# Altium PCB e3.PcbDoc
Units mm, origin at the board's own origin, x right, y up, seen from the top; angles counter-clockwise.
Board outline 100 x 60 mm, 2 copper layers (Top Layer, Bottom Layer), stack 0.325 mm thick; 68 components, 138 nets, 434 pads, 129 vias.
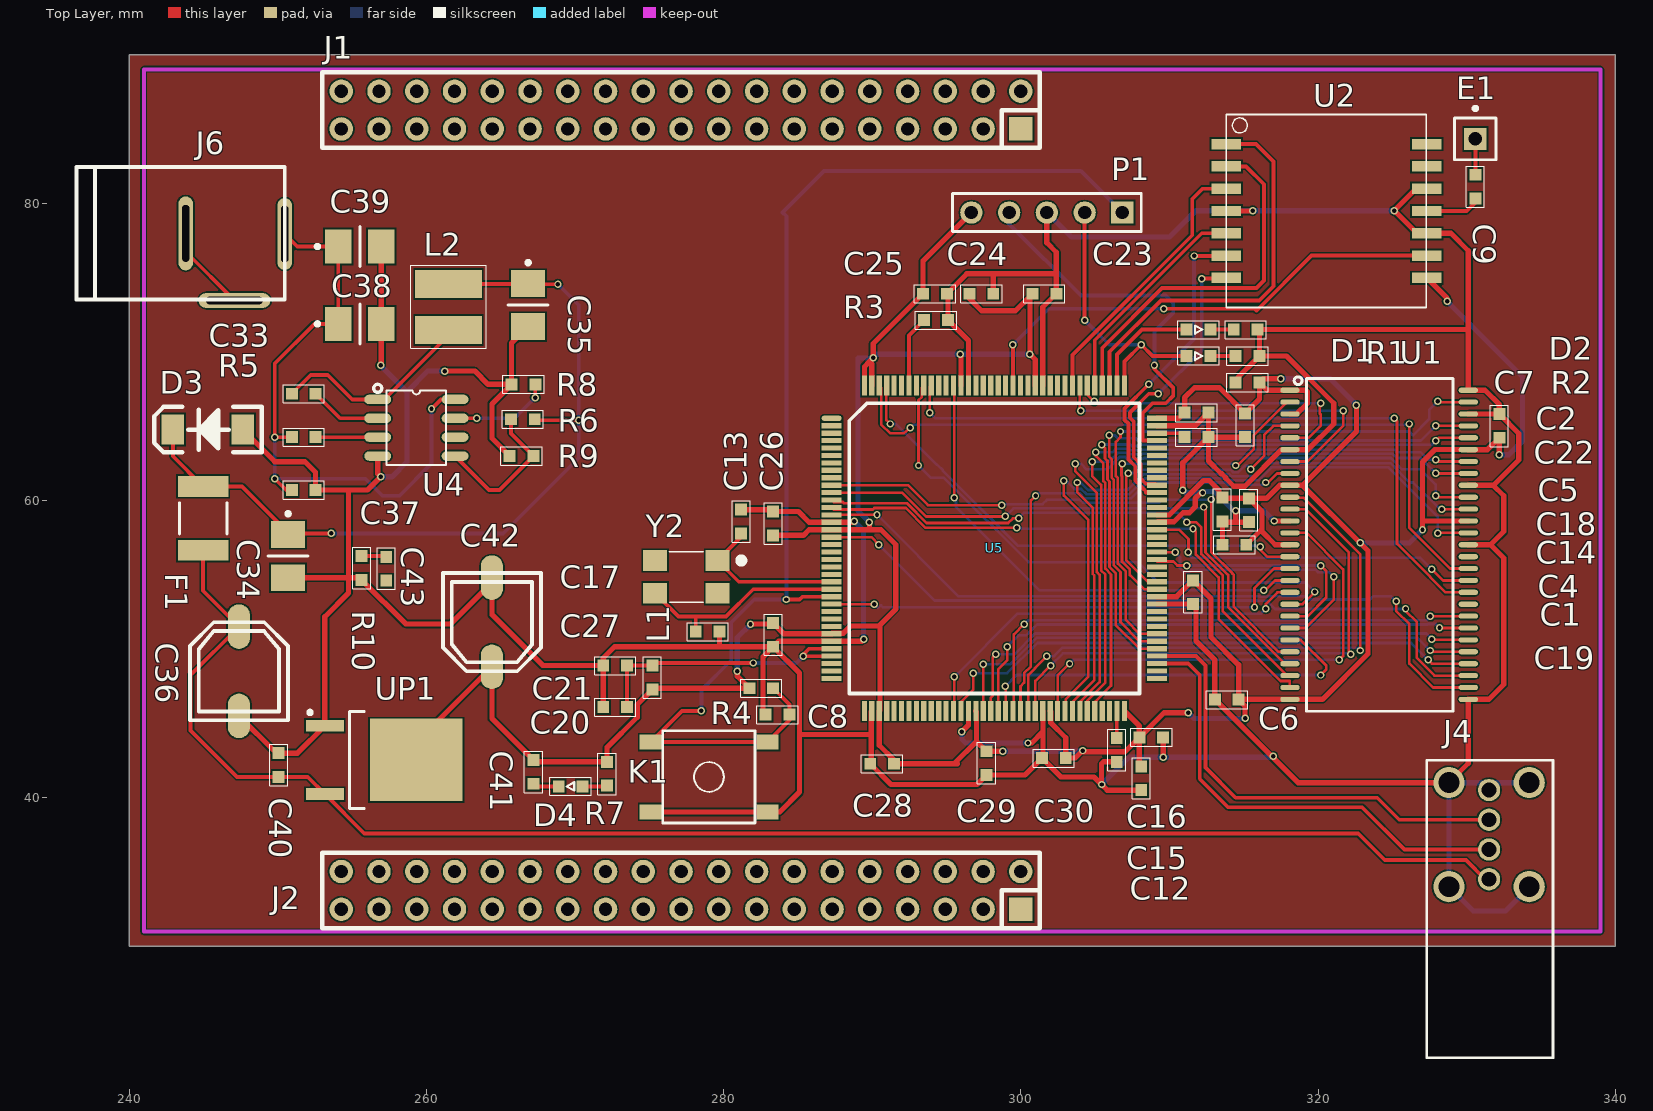
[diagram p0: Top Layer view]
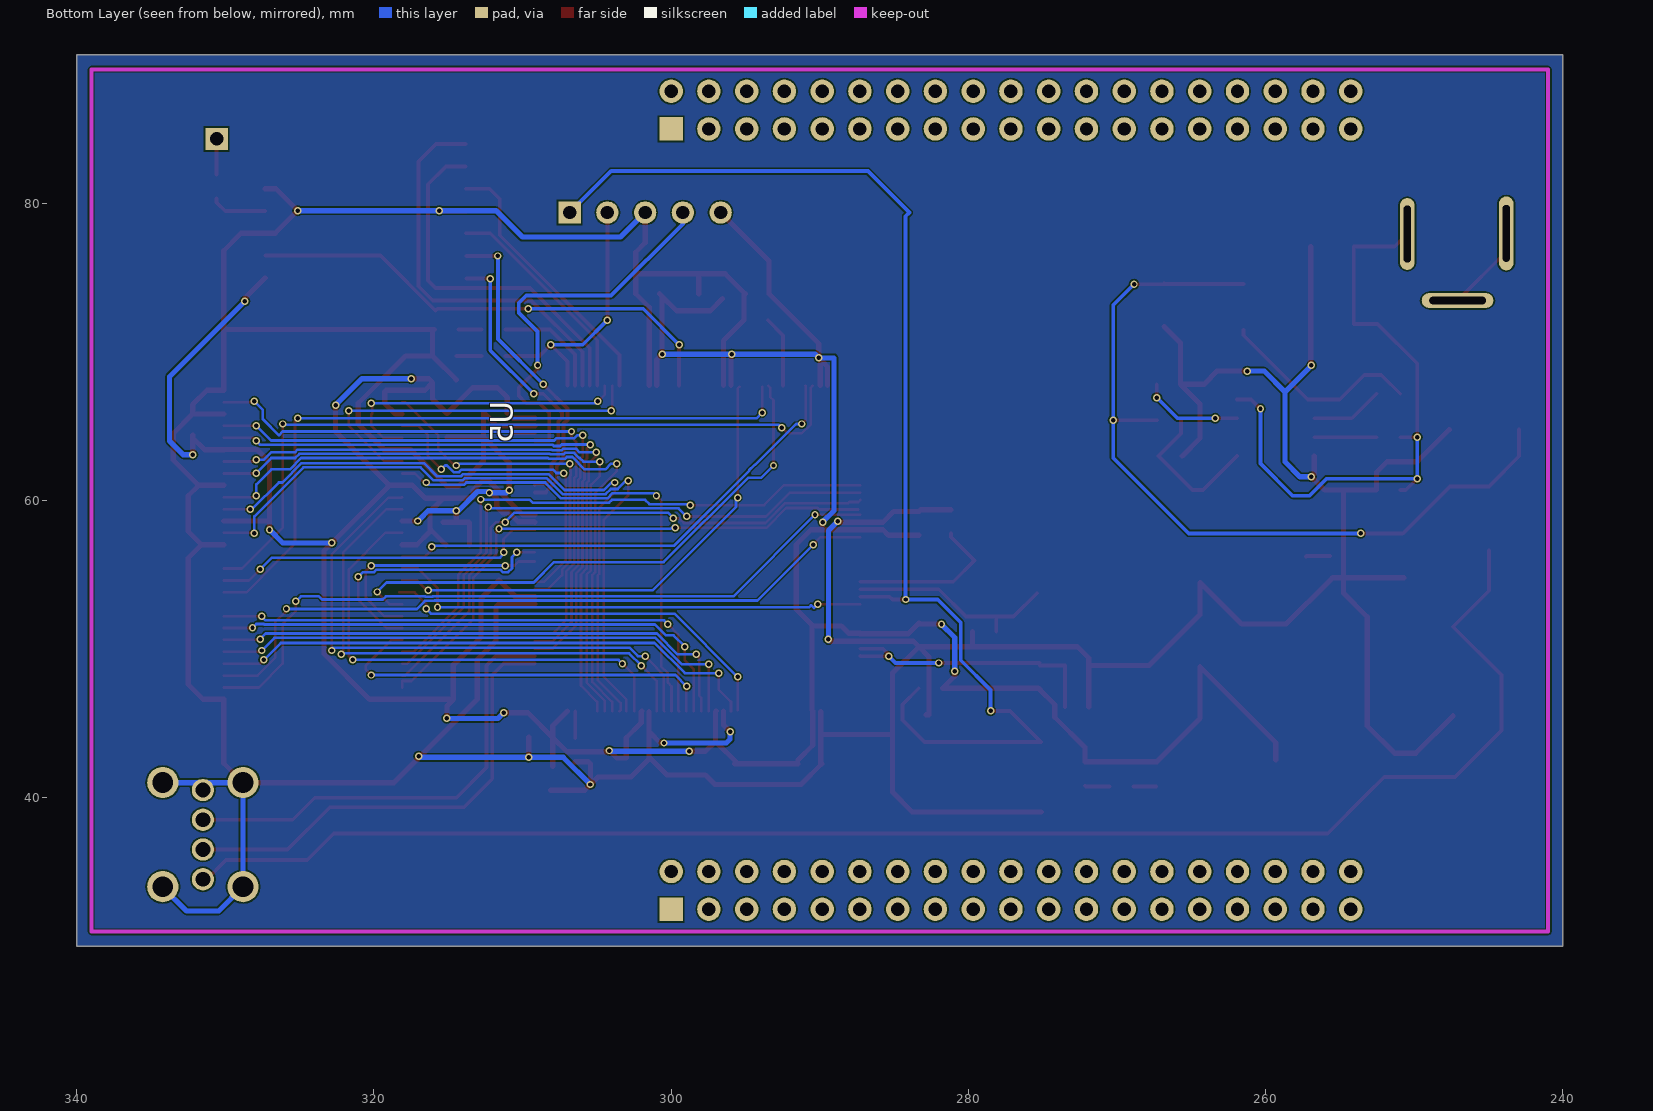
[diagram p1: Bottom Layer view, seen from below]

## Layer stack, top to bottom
Top Solder: solder mask 0.0102, Solder Resist, Dk 3.5
Top Layer: signal copper 0.0356
Dielectric 1: core 0.254, FR-4, Dk 4.2
Bottom Layer: signal copper 0.0356
Bottom Solder: solder mask 0.0102, Solder Resist, Dk 3.5

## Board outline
240,30 240,90 340,90 340,30

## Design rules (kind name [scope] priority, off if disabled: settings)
Clearance GND [All] p1: gap=0.104
HoleSize [All] p1: absolutevalues=TRUE maxlimit=4.5 minlimit=0.3 maxpercent=80.000 minpercent=20.000
HoleToHoleClearance [All] p1: gap=0.1 allowstackedmicrovias=TRUE
MinimumSolderMaskSliver [All] p1: minsoldermaskwidth=0.01
PolygonConnect [IsVia] p1: connectstyle=Direct reliefconductorwidth=0.254 reliefentries=4 polygonreliefangle="90 Angle" airgapwidth=0.254
RoomDefinition Sheet1 [InComponentClass('Sheet1')] p1: confinementstyle=ConfineIn formatcopy=TRUE lockcomponents=FALSE outline 235.077,0 337.185,0 337.185,91.44 235.077,91.44
RoutingVias [All] p1: holewidth=0.3 width=0.5 viastyle="Through Hole" minholewidth=0.1 minwidth=0.3 maxholewidth=0.6 maxwidth=1
SilkToSilkClearance [All] p1: silktosilkclearance=0.01
SilkToSolderMaskClearance [IsPad] p1: minsilkscreentomaskgap=0 clearancetoexposedcopper=FALSE
SolderMaskExpansion [All] p1: expansion=0.102
Width Width_3 [InNetClass('SDIO')] p1: maxlimit=0.254 minlimit=0.254 preferedwidth=0.254
Width Width_1 [InNetClass('SDRAM')] p2: maxlimit=0.254 minlimit=0.153 preferedwidth=0.177
Width Width_2 [InNet('GND')] p3: maxlimit=0.454 minlimit=0.254 preferedwidth=0.354
Width [InNet('3.3V')] p4: maxlimit=0.354 minlimit=0.254 preferedwidth=0.354
25 further rules are at their usual default settings.

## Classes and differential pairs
component class Sheet1: C2 C5 C6 C7 C8 C9 C12 C13 C15 C16 C17 C20 C21 C22 C23 C24 C25 C26 C27 C28 C29 C30 C33 C34 C35 C36 C37 C38 C39 C40 C41 C42 C43 D1 D2 D3 D4 E1 F1 J1 J2 J4 J6 K1 L1 L2 P1 R1 R2 R3 R4 R5 R6 R7 R8 R9 R10 U1 U2 U4 U5 UP1 Y2
net class WIFI: NetU2_1 NetU2_2 NetU2_3 NetU2_5 NetU2_6 NetU2_7 NetU2_9
net class SDRAM: NetU1_2 NetU1_4 NetU1_5 NetU1_7 NetU1_8 NetU1_10 NetU1_11 NetU1_13 NetU1_15 NetU1_16 NetU1_17 NetU1_18 NetU1_19 NetU1_20 NetU1_21 NetU1_22 NetU1_23 NetU1_24 NetU1_25 NetU1_26 NetU1_29 NetU1_30 NetU1_31 NetU1_32 NetU1_33 NetU1_34 NetU1_35 NetU1_37 NetU1_38 NetU1_39 NetU1_42 NetU1_44 NetU1_45 NetU1_47 NetU1_48 NetU1_50 NetU1_51 NetU1_53

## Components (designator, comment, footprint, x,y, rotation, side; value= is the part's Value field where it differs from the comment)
C1 "C_0.1UF_0603" C_0603 313.563,57.023 r0 top
C2 "C_0.1UF_0603" C_0603 314.452,67.945 r0 top
C4 "C_0.1UF_0603" C_0603 315.341,58.547 r90 top
C5 "C_0.1UF_0603" C_0603 315.087,64.262 r90 top
C6 "C_0.1UF_0603" C_0603 313.055,46.609 r0 top
C7 "C_0.1UF_0603" C_0603 332.195,65.823 r270 top
C8 "C_0.1UF_0603" C_0603 282.829,45.593 r0 top
C9 "CAP_NP" R_0603 330.581,81.915 r270 top
C12 "C_2.2UF_0603" CAP_0603_FIRE 306.451,42.418 r90 top
C13 "C_22P_0603" C_0603 281.178,57.785 r90 top
C14 "C_2.2UF_0603" CAP_0603_FIRE 311.023,64.262 r0 top
C15 "C_0.1UF_0603" C_0603 307.975,44.069 r0 top
C16 "C_0.1UF_0603" C_0603 308.102,40.513 r90 top
C17 "C_22P_0603" C_0603 278.13,51.181 r0 top
C18 "C_0.1UF_0603" C_0603 313.563,60.198 r270 top
C19 "C_0.1UF_0603" C_0603 311.585,53.032 r90 top
C20 "C_0.1UF_0603" C_0603 271.907,46.101 r0 top
C21 "C_0.1UF_0603" C_0603 271.907,48.895 r0 top
C22 "C_0.1UF_0603" C_0603 311.023,65.913 r0 top
C23 "C_0.1UF_0603" C_0603 302.387,73.914 r180 top
C24 "C_0.1UF_0603" C_0603 296.545,73.914 r0 top
C25 "C_0.1UF_0603" C_0603 295.021,73.914 r180 top
C26 "C_0.1UF_0603" C_0603 283.337,57.658 r90 top
C27 "C_0.1UF_0603" C_0603 283.337,50.165 r90 top
C28 "C_0.1UF_0603" C_0603 291.465,42.291 r180 top
C29 "C_0.1UF_0603" C_0603 297.688,41.529 r90 top
C30 "C_0.1UF_0603" C_0603 303.022,42.672 r180 top
C33 "C_0.1UF_0603" C_0603 250.952,67.183 r0 top
C34 "C+_10UF_B" AVX_B_3528-21 250.698,56.261 r270 top
C35 "C+_10UF_B" AVX_B_3528-21 266.849,73.152 r270 top
C36 "CAP+_47UF_6.5X6.5" EC_47UF_6.5X6.5 247.396,48.514 r0 top
C37 "C_0.1UF_0603" C_0603 250.952,60.706 r0 top
C38 "C+_10UF_B" AVX_B_3528-21 255.524,71.882 r0 top
C39 "C+_10UF_B" AVX_B_3528-21 255.524,77.089 r0 top
C40 "C_0.1UF_0603" C_0603 250.063,41.402 r90 top
C41 "C_0.1UF_0603" C_0603 267.208,42.545 r270 top
C42 "CAP+_47UF_6.5X6.5" EC_47UF_6.5X6.5 264.414,51.816 r180 top
C43 "C_2.7NF_0603" C_0603 257.302,54.61 r90 top
D1 "LED_BLUE_0603" LED_0603 311.15,71.501 r0 top
D2 "LED_RED_0603" LED_0603 311.15,69.723 r0 top
D3 "SMAJ5.0CA" DO-214 247.65,64.77 r180 top
D4 "LED_RED_0603" LED_0603 270.51,40.767 r180 top
E1 "Antenna" PIN1 330.581,84.328 r0 top
F1 "FUSE500MA" C1812 244.983,58.801 r270 top
J1 "2X19PIN_DIP" 2X19X2.54MM 300,85 r90 top
J2 "2X19PIN_DIP" 2X19X2.54MM 300,32.5 r90 top
J4 "USB-AF90" USB-AF90 328.803,41.021 r270 top
J6 "DC-005" DC-005 236.474,73.533 r0 top
K1 "KEY" SW6.2/6.2-SMD 279.019,41.402 r0 top
L1 "BEAD-0603" R_0603 275.209,48.895 r270 top
L2 "L_6.8UH_4532" GDCD4532 261.493,73.025 r90 top
P1 "Header 5" HDR1X5 306.832,79.375 r180 top
R1 "R_1K_0603" R_0603 314.325,71.501 r0 top
R2 "R_1K_0603" R_0603 314.452,69.723 r0 top
R3 "R_10K_0603" R_0603 293.497,72.136 r0 top
R4 "R_10K_0603" R_0603 283.337,47.371 r180 top
R5 "R_100K_0603" R_0603 250.952,64.262 r0 top
R6 "R_62K_0603" R_0603 267.297,65.468 r180 top
R7 "R_1K_0603" R_0603 272.161,42.418 r270 top
R8 "R_180K_0603" R_0603 267.335,67.818 r180 top
R9 "R_11.8K_0603" R_0603 267.208,62.992 r180 top
R10 "R_24K_0603" R_0603 255.651,56.261 r270 top
U1 "IS42S16400J" TSOP-54 324.104,57.023 r0 top
U2 "BL-8782" BL-8782 313.817,85.979 r0 top
U4 "RT7272" RT7272 259.334,64.897 r0 top
U5 "STM32F429_144" 429_144 287.274,65.532 r0 top
UP1 "1086-3.3" TO-252-2L 257.175,42.545 r0 top
Y2 "CRYSTAL_25MHZ" CRYSTAL_25MHZ 277.495,54.864 r180 top

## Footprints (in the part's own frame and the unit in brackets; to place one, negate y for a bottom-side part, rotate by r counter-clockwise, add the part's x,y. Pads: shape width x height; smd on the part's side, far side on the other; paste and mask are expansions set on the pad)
2X19X2.54MM [mil]
  rrect0% 62x62 all layers, no hole: 1(0,0)
  round 62 hole 35.43: 2(100,0) 3(0,100) 4(100,100) 5(0,200) 6(100,200) 7(0,300) 8(100,300) 9(0,400) 10(100,400) 11(0,500) 12(100,500) 13(0,600) 14(100,600) 15(0,700) 16(100,700) 17(0,800) 18(100,800) 19(0,900) 20(100,900) 21(0,1000) 22(100,1000) 23(0,1100) 24(100,1100) 25(0,1200) 26(100,1200) 27(0,1300) 28(100,1300) 29(0,1400) 30(100,1400) 31(0,1500) 32(100,1500) 33(0,1600) 34(100,1600) 35(0,1700) 36(100,1700) 37(0,1800) 38(100,1800)
  silkscreen extent -50,-50 150,1850
429_144 [mm]
  oval 1.35x0.35 smd: 1(0,0)
  rect 1.35x0.35 smd: 2(0,-0.5) 3(0,-1) 4(0,-1.5) 5(0,-2) 6(0,-2.5) 7(0,-3) 8(0,-3.5) 9(0,-4) 10(0,-4.5) 11(0,-5) 12(0,-5.5) 13(0,-6) 14(0,-6.5) 15(0,-7) 16(0,-7.5) 17(0,-8) 18(0,-8.5) 19(0,-9) 20(0,-9.5) 21(0,-10) 22(0,-10.5) 23(0,-11) 24(0,-11.5) 25(0,-12) 26(0,-12.5) 27(0,-13) 28(0,-13.5) 29(0,-14) 30(0,-14.5) 31(0,-15) 32(0,-15.5) 33(0,-16) 34(0,-16.5) 35(0,-17) 36(0,-17.5) 73(21.9,-17.5) 74(21.9,-17) 75(21.9,-16.5) 76(21.9,-16) 77(21.9,-15.5) 78(21.9,-15) 79(21.9,-14.5) 80(21.9,-14) 81(21.9,-13.5) 82(21.9,-13) 83(21.9,-12.5) 84(21.9,-12) 85(21.9,-11.5) 86(21.9,-11) 87(21.9,-10.5) 88(21.9,-10) 89(21.9,-9.5) 90(21.9,-9) 91(21.9,-8.5) 92(21.9,-8) 93(21.9,-7.5) 94(21.9,-7) 95(21.9,-6.5) 96(21.9,-6) 97(21.9,-5.5) 98(21.9,-5) 99(21.9,-4.5) 100(21.9,-4) 101(21.9,-3.5) 102(21.9,-3) 103(21.9,-2.5) 104(21.9,-2) 105(21.9,-1.5) 106(21.9,-1) 107(21.9,-0.5) 108(21.9,0)
  rect 0.35x1.35 smd: 37(2.2,-19.7) 38(2.7,-19.7) 39(3.2,-19.7) 40(3.7,-19.7) 41(4.2,-19.7) 42(4.7,-19.7) 43(5.2,-19.7) 44(5.7,-19.7) 45(6.2,-19.7) 46(6.7,-19.7) 47(7.2,-19.7) 48(7.7,-19.7) 49(8.2,-19.7) 50(8.7,-19.7) 51(9.2,-19.7) 52(9.7,-19.7) 53(10.2,-19.7) 54(10.7,-19.7) 55(11.2,-19.7) 56(11.7,-19.7) 57(12.2,-19.7) 58(12.7,-19.7) 59(13.2,-19.7) 60(13.7,-19.7) 61(14.2,-19.7) 62(14.7,-19.7) 63(15.2,-19.7) 64(15.7,-19.7) 65(16.2,-19.7) 66(16.7,-19.7) 67(17.2,-19.7) 68(17.7,-19.7) 69(18.2,-19.7) 70(18.7,-19.7) 71(19.2,-19.7) 72(19.7,-19.7) 109(19.7,2.2) 110(19.2,2.2) 111(18.7,2.2) 112(18.2,2.2) 113(17.7,2.2) 114(17.2,2.2) 115(16.7,2.2) 116(16.2,2.2) 117(15.7,2.2) 118(15.2,2.2) 119(14.7,2.2) 120(14.2,2.2) 121(13.7,2.2) 122(13.2,2.2) 123(12.7,2.2) 124(12.2,2.2) 125(11.7,2.2) 126(11.2,2.2) 127(10.7,2.2) 128(10.2,2.2) 129(9.7,2.2) 130(9.2,2.2) 131(8.7,2.2) 132(8.2,2.2) 133(7.7,2.2) 134(7.2,2.2) 135(6.7,2.2) 136(6.2,2.2) 137(5.7,2.2) 138(5.2,2.2) 139(4.7,2.2) 140(4.2,2.2) 141(3.7,2.2) 142(3.2,2.2) 143(2.7,2.2) 144(2.2,2.2)
  silkscreen extent 1.19,-18.51 20.71,1.01
AVX_B_3528-21 [mm]
  rect 1.8x2.3 smd: 1(-1.45,0) 2(1.45,0)
  silkscreen extent -2.97,-1.35 0,1.35
BL-8782 [mm]
  rect 2x0.7 smd: 1(0,-2) 2(0,-3.5) 3(0,-5) 4(0,-6.5) 5(0,-8) 6(0,-9.5) 7(0,-11) 8(13.5,-11) 9(13.5,-9.5) 10(13.5,-8) 11(13.5,-6.5) 12(13.5,-5) 13(13.5,-3.5) 14(13.5,-2)
  silkscreen extent 0,-13 13.46,0
C1812 [mm]
  rect 1.4x3.4 smd: 1(-2.15,0) 2(2.15,0)
  silkscreen extent -1.05,-1.6 1.05,1.6
C_0603 [mm]
  rect 0.8x0.8 smd: 1(0,0) 2(1.6,0)
  silkscreen extent -0.58,-0.61 2.2,0.61
CAP_0603_FIRE [mm]
  rect 0.8x0.8 smd: 1(0,0) 2(1.6,0)
  silkscreen extent -0.58,-0.61 2.2,0.61
CRYSTAL_25MHZ [mm]
  rect 1.6x1.4 smd: 1(-2.1,-1.1) 2(2.1,-1.1) 3(2.1,1.1) 4(-2.1,1.1)
  silkscreen extent -3.8,-1.7 1.13,1.7
DC-005 [mm]
  oval 1x4.826 hole 0.5 slot 3.81 at 90 deg: 1(14,4.399)
  oval 1x4.978 hole 0.5 slot 3.81 at 90 deg: 2(7.341,4.445)
  oval 4.826x1 hole 0.5 slot 3.81 at 0 deg: 3(10.617,-0.076)
  silkscreen extent 0,0 14,8.9
DO-214 [mil]
  rect 60x80 smd: 1(0,0) 2(185,0)
  silkscreen extent -50,-60 235,60
EC_47UF_6.5X6.5 [mm]
  oval 1.5x3 smd: 1(0,3) 2(0,-3)
  silkscreen extent -3.3,-3.3 3.3,3.3
GDCD4532 [mm]
  rect 1.9x4.5 smd: 1(-1.55,0) 2(1.55,0)
  silkscreen extent -2.79,-2.54 2.79,2.54
HDR1X5 [mm] "Connector; Header; 5 Position"
  rect 1.5x1.5 hole 0.9: 1(0,0)
  round 1.5 hole 0.9: 2(2.54,0) 3(5.08,0) 4(7.62,0) 5(10.16,0)
  silkscreen extent -1.27,-1.27 11.43,1.27
LED_0603 [mm]
  rect 0.8x0.8 smd: A(0,0) K(1.6,0)
  silkscreen extent -0.58,-0.6 2.19,0.61
PIN1 [mm] "Generic Antenna; 1 Lead"
  rect 1.5x1.5 hole 0.9: 1(0,0)
  silkscreen extent -1.4,-1.4 1.4,2.17
R_0603 [mm]
  rect 0.8x0.8 smd: 1(0,0) 2(1.6,0)
  silkscreen extent -0.58,-0.61 2.2,0.61
RT7272 [mm]
  oval 1.8x0.635 smd: 1(-2.6,1.905) 2(-2.6,0.635) 3(-2.6,-0.635) 4(-2.6,-1.905) 5(2.6,-1.905) 6(2.6,-0.635) 7(2.6,0.635) 8(2.6,1.905)
  silkscreen extent -2.87,-2.5 2,2.92
SW6.2/6.2-SMD [mm]
  rect 1.5x1 smd: 1(-3.912,2.35) 2(3.937,2.35) 3(-3.912,-2.35) 4(3.937,-2.35)
  silkscreen extent -3.1,-3.1 3.1,3.1
TO-252-2L [mm]
  rect 2.55x0.8 smd: 1(-4,2.3) 3(-4,-2.3)
  rect 6.25x5.55 smd: 2(2.15,0)
  silkscreen extent -5.12,-3.25 -1.35,3.32
TSOP-54 [mm]
  oval 1.3x0.35 smd: 1(-6,10.4) 2(-6,9.6) 3(-6,8.8) 4(-6,8) 5(-6,7.2) 6(-6,6.4) 7(-6,5.6) 8(-6,4.8) 9(-6,4) 10(-6,3.2) 11(-6,2.4) 12(-6,1.6) 13(-6,0.8) 14(-6,0) 15(-6,-0.8) 16(-6,-1.6) 17(-6,-2.4) 18(-6,-3.2) 19(-6,-4) 20(-6,-4.8) 21(-6,-5.6) 22(-6,-6.4) 23(-6,-7.2) 24(-6,-8) 25(-6,-8.8) 26(-6,-9.6) 27(-6,-10.4) 28(6,-10.4) 29(6,-9.6) 30(6,-8.8) 31(6,-8) 32(6,-7.2) 33(6,-6.4) 34(6,-5.6) 35(6,-4.8) 36(6,-4) 37(6,-3.2) 38(6,-2.4) 39(6,-1.6) 40(6,-0.8) 41(6,0) 42(6,0.8) 43(6,1.6) 44(6,2.4) 45(6,3.2) 46(6,4) 47(6,4.8) 48(6,5.6) 49(6,6.4) 50(6,7.2) 51(6,8) 52(6,8.8) 53(6,9.6) 54(6,10.4)
  silkscreen extent -5.71,-11.2 4.96,11.3
USB-AF90 [mm]
  rrect100% 1.5x1.5 hole 1: 1(6.5,2.7) 2(4.5,2.7) 3(2.5,2.7) 4(0.5,2.7)
  rrect100% 2.1x2.1 hole 1.4: 5(0,0) 6(7,0) 7(7,5.4) 8(0,5.4)
  silkscreen extent -1.5,-1.5 18.5,7

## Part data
C9: "0603, X7R, 50V, 10%(K)"
D3: "SMAJ5.0CA-E3/61 400W 5V"
E1: "Generic Antenna"
F1: "FUSE500ma"
P1: "Header, 5-Pin"

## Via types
v1: diameter 0.5, hole 0.3, Top Layer to Bottom Layer, 129 vias

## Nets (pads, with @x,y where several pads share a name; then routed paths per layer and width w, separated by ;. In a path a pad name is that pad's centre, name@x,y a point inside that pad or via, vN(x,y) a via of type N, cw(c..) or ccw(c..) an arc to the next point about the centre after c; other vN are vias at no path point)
3.3V: C1.2 C2.2 C4.2 C5.2 C6.2 C7.2 C15.1 C16.2 C18.1 C19.2 C22.1 C23.2 C24.1 C25.2 C26.1 C27.2 C28.1 C29.2 C30.1 C41.1 C42.1 L1.2 P1.5 R4.2 R7.1 U1.1 U1.3 U1.9 U1.14 U1.27 U1.43 U1.49 U2.8 U5.16 U5.30 U5.39 U5.52 U5.62 U5.72 U5.84 U5.95 U5.108 U5.121 U5.131 U5.143 U5.144 UP1.2 | length 282.6
  Top Layer w0.354: UP1.2 259.325,43.727 C42.1 264.414,45.339 C41.1 267.335,42.418 R7.1 272.161,43.393 274.188,45.42 274.188,46.274 L1.2 275.285,47.371 R4.2 280.924,48.184 v1(280.924,48.514) ; v1(281.813,51.689) 283.261,51.689 C27.2 284.07,51.032 U5.30 287.318,51.076 288.065,51.076 288.551,51.562 290.449,51.562 291.592,52.705 291.592,57.023 290.576,58.039 289.814,58.039 v1(289.814,58.547) ; C26.1 285.369,57.658 285.743,58.032 U5.16 289.814,58.032 ; U5.144 289.474,69.002 289.814,69.342 ; U5.143 289.974,69.182 289.814,69.342 ; 290.518,51.562 290.518,45.876 U5.39 290.474,43.536 C28.1@291.465,42.545 ; C28.1 295.51,42.291 ; 295.729,42.291 295.51,42.291 ; v1(295.91,69.85) 295.974,69.786 U5.131 ; C24.1@296.545,73.584 297.358,72.771 299.644,72.771 C23.2@300.609,73.736 ; P1.5 293.421,76.124 C25.2 290.068,70.561 v1(290.068,69.596) 289.814,69.342 ; U5.52 297.018,45.788 297.018,43.799 ; v1(298.78,43.129) C29.2 297.018,43.799 ; C23.2 C23.2@300.609,73.736 ; U5.121 300.974,69.485 v1(300.609,69.85) C23.2@300.609,73.736 ; U5.62 302.018,45.788 302.018,45.041 303.022,44.037 C30.1 303.657,42.672 v1(304.165,43.18) 304.165,43.099 307.005,43.099 C15.1 ; U5.72 307.975,44.831 C15.1 ; C16.2@307.975,42.113 C15.1 ; U5.84 310.485,53.532 C19.2 312.801,53.416 312.801,50.8 314.655,48.946 C6.2 ; U5.95 309.984,59.032 312.293,61.341 312.674,61.341 313.332,60.683 313.332,60.198 C18.1 ; U5.108 310.642,65.532 C22.1 311.023,66.929 311.681,67.587 313.362,67.587 C5.2 316.052,66.827 C2.2 ; v1(311.277,45.72) 309.626,45.72 C15.1 ; C18.1@313.614,60.147 C4.2 ; v1(315.087,45.339) 315.087,46.177 C6.2 ; C1.2 316.204,58.065 ; v1(317.5,68.199) 316.306,68.199 C2.2 ; U1.14 317.119,57.023 316.23,57.912 316.23,59.258 C4.2 ; U1.3 318.553,65.823 319.278,66.548 319.278,67.31 319.165,67.423 U1.1 316.574,67.423 C2.2 ; v1(322.58,66.421) 322.58,64.642 318.961,61.023 ; v1(327.025,58.039) 327.025,58.623 ; U2.8 328.676,73.62 v1(328.676,73.406) ; U1.49@330.096,63.431 327.856,63.431 327.025,62.6 327.025,58.623 ; U1.43 327.025,58.623 ; U1.49 331.395,63.423 C7.2 ; v1(332.195,63.08) C7.2 ; C7.2@332.195,64.401 C7.2 ; 295.51,42.291 297.018,43.799 ; C6.2 314.669,46.623 U1.27 320.297,46.623 323.365,49.691 323.365,56.619 v1(322.834,57.15) 318.961,61.023 ; C4.2 316.535,60.147 317.411,61.023 U1.9 318.961,61.023
  Bottom Layer w0.354: v1(280.924,48.514) 280.924,50.773 281.813,51.662 v1(281.813,51.689) ; v1(289.814,58.547) 289.052,59.309 289.052,69.596 v1(290.068,69.596) 290.322,69.85 v1(295.91,69.85) v1(300.609,69.85) ; v1(298.78,43.129) 304.114,43.129 v1(304.165,43.18) ; v1(311.277,45.72) 311.658,45.339 v1(315.087,45.339) ; v1(317.5,68.199) 320.802,68.199 v1(322.58,66.421) ; v1(322.834,57.15) 326.136,57.15 v1(327.025,58.039) ; v1(328.676,73.406) 333.756,68.326 333.756,64.008 332.9,63.152 ; v1(332.195,63.08) 332.828,63.08
5V: C36.1 C40.1 F1.2 J4.1 UP1.3 | length 106
  Top Layer w0.254: F1.2 244.983,53.927 C36.1 244.142,48.26 244.142,44.529 247.269,41.402 C40.1 252.018,41.402 UP1.3 255.828,37.592 322.707,37.592 324.485,35.814 329.946,35.814 331.239,34.521 J4.1
GND: C1.1 C2.1 C4.1 C5.1 C6.1 C7.1 C8.1 C12.1 C13.2 C14.2 C15.2 C16.1 C17.2 C18.2 C19.1 C20.1 C21.1 C22.2 C23.1 C24.2 C25.1 C26.2 C27.1 C28.2 C29.1 C30.2 C34.2 C35.2 C36.2 C37.2 C38.2 C39.2 C40.2 C42.2 D3.1 J4.4 J4.5 J4.6 J4.7 J4.8 K1.3 K1.4 P1.3 R1.2 R2.2 R3.2 R8.2 R9.2 R10.2 U1.6 U1.12 U1.28 U1.41 U1.46 U1.52 U1.54 U2.4 U2.10 U2.12 U4.4 U5.15 U5.31 U5.38 U5.51 U5.61 U5.83 U5.94 U5.107 U5.120 U5.130 UP1.1 | length 445.3
  Top Layer w0.354: C36.2 249.908,43.002 C40.2 251.332,43.002 UP1.1 253.175,52.185 254.762,53.772 254.762,54.811 ; D3.1 249.809,62.611 251.841,62.611 252.552,61.9 C37.2 254.762,60.706 ; C34.2 254.686,54.811 ; U4.4 256.734,61.782 v1(256.921,61.595) 256.032,60.706 254.762,60.706 ; v1(256.921,69.088) 256.974,69.141 C38.2 C39.2 ; v1(261.239,68.707) 263.271,68.707 264.16,67.818 R8.2 ; R9.2 264.414,64.186 264.414,66.497 R8.2 ; C35.2 265.735,70.588 R8.2 ; C20.1 C21.1 ; K1.3 K1.4 283.776,39.052 285.11,40.386 285.11,44.259 ; 279.73,50.241 C17.2 ; C13.2 283.21,59.385 C26.2 285.039,59.258 285.765,58.532 U5.15 288.783,58.532 288.798,58.547 v1(288.798,58.593) ; C8.1 282.656,45.593 282.656,49.484 C27.1 ; v1(289.433,50.673) 289.292,50.532 U5.31 283.704,50.532 C27.1 ; U5.38@289.93,45.788 289.93,44.196 ; v1(296.037,44.45) 296.474,44.887 U5.51 ; U5.130 296.474,70.759 R3.2 295.097,73.838 C25.1 296.367,75.26 298.145,75.26 ; C24.2 298.145,75.26 ; v1(300.482,43.688) 300.736,43.688 301.498,44.45 ; U5.120 301.474,73.001 C23.1 302.387,76.708 301.752,77.343 P1.3 ; C30.2@301.498,42.748 301.498,44.45 ; U5.61@301.498,45.808 301.498,44.45 ; 302.336,75.26 298.145,75.26 ; C12.1 305.562,42.418 305.435,42.291 v1(305.435,40.894) ; C16.1 305.816,40.513 v1(305.435,40.894) ; U5.83 C19.1 311.785,52.832 311.785,50.546 313.055,49.276 C6.1 318.643,41.021 J4.5 330.104,42.322 U1.28 331.484,46.623 332.486,47.625 332.486,56.134 331.597,57.023 ; U5.94 309.216,58.574 310.301,58.574 310.909,59.182 311.347,59.182 311.728,59.563 311.728,60.128 312.121,60.521 v1(312.224,60.521) ; U5.107 311.742,65.032 C22.2 C14.2 ; v1(309.575,42.723) C15.2 ; v1(310.896,60.706) 310.896,62.535 C14.2 ; C1.1 313.563,58.496 313.614,58.547 314.452,58.547 ; U2.4 315.572,79.479 v1(315.595,79.502) ; v1(314.452,59.309) 314.452,58.547 ; C2.1@314.452,68.123 R2.2 ; C5.1 C14.2 ; C4.1 314.452,58.547 ; R1.2 330.104,71.501 ; R1.2@316.052,71.374 R2.2 ; v1(317.043,58.623) U1.12 ; U2.12 326.597,80.979 v1(325.12,79.502) 326.643,77.979 U2.10 328.929,77.979 330.104,76.804 330.104,71.501 ; U1.41 331.597,57.023 ; U1.46 331.788,61.023 ; U1.52 C7.1 ; 254.762,54.811 254.762,60.706 ; 254.762,54.811 255.501,54.811 R10.2 258.623,51.689 261.62,51.689 264.414,54.483 264.414,52.324 267.843,48.895 C21.1 ; C21.1 271.907,49.403 272.669,50.165 C27.1 ; C27.1 285.11,48.392 285.11,44.259 ; 285.11,44.259 289.867,44.259 289.93,44.196 ; 289.93,44.196 289.93,42.356 C28.2 291.262,40.894 297.053,40.894 C29.1 300.279,41.529 C30.2 302.692,41.402 304.927,41.402 v1(305.435,40.894) ; C14.2 312.623,62.662 313.486,61.799 313.522,61.799 313.79,61.531 313.79,61.495 314.325,60.96 315.076,60.96 317.539,63.423 U1.6 319.328,63.423 321.056,65.151 321.056,66.548 317.881,69.723 R2.2 ; 330.104,71.501 U1.54 331.23,67.423 332.195,66.458 C7.1 ; 331.597,57.023 332.486,57.912 332.486,60.325 331.788,61.023 ; 331.788,61.023 333.502,62.737 333.502,64.516 C7.1
  Bottom Layer w0.354: v1(256.921,61.595) 257.683,61.595 258.699,62.611 258.699,67.31 ; v1(256.921,69.088) 258.699,67.31 ; v1(261.239,68.707) 260.096,68.707 258.699,67.31 ; v1(288.798,58.593) 289.41,57.981 v1@289.41,50.569 ; v1(296.037,44.45) 296.037,43.942 296.291,43.688 v1(300.482,43.688) ; P1.3 303.403,77.724 310.007,77.724 311.785,79.502 v1(315.595,79.502) v1(325.12,79.502) ; v1(305.435,40.894) 307.264,42.723 v1(309.575,42.723) 316.916,42.723 v1(316.992,42.799) ; v1(310.896,60.706) 311.081,60.521 v1(312.224,60.521) 312.305,60.602 313.021,60.602 314.314,59.309 v1(314.452,59.309) 316.357,59.309 316.865,58.801 ; J4.7 334.203,33.975 332.613,32.385 330.439,32.385 J4.6 J4.5 J4.8
NetC8_2: C8.2 K1.1 K1.2 P1.1 R4.1 U5.25 | length 82.6
  Top Layer w0.254: v1(278.511,45.847) 277.202,45.847 K1.1 K1.2 284.429,45.225 C8.2 284.429,46.279 R4.1 ; v1(284.226,53.34) 285.112,53.34 285.304,53.532 U5.25
  Bottom Layer w0.254: v1(278.511,45.847) 278.511,47.244 280.516,49.249 280.516,51.789 282.067,53.34 v1(284.226,53.34) 284.226,79.121 283.972,79.375 286.766,82.169 304.038,82.169 P1.1 P1.1@306.832,79.144
NetC9_1: C9.1 E1.1 | length 2.4
  Top Layer w0.254: C9.1 E1.1
NetC9_2: C9.2 U2.11 | length 3.8
  Top Layer w0.254: U2.11 329.999,79.479 330.581,80.061 C9.2
NetC12_2: C12.2 U5.71 | length 1.8
  Top Layer w0.254: C12.2 U5.71@306.451,45.809
NetC13_1: C13.1 U5.23 Y2.1 | length 10.7
  Top Layer w0.254: C13.1 281.178,57.547 Y2.1 281.027,54.532 U5.23
NetC14_1: C14.1 U5.106 | length 2
  Top Layer w0.254: U5.106 310.753,64.532 C14.1
NetC17_1: C17.1 U5.24 Y2.3 | length 14.3
  Top Layer w0.254: Y2.3 276.962,52.197 278.13,52.197 ; C17.1 278.13,52.197 ; U5.24 281.997,54.032 280.162,52.197 278.13,52.197
NetC20_2: C20.2 C21.2 L1.1 U5.32 U5.33 | length 19
  Top Layer w0.254: C20.2 C21.2 L1.1 275.209,49.071 v1(281.989,49.071) ; v1(285.369,49.53) 287.272,49.53 U5.33 ; v1@285.369,49.645 285.756,50.032 U5.32
  Bottom Layer w0.254: v1(281.989,49.071) 284.91,49.071 v1(285.369,49.53)
NetC33_1: C33.1 L2.1 U4.1 | length 13.9
  Top Layer w0.254: C33.1 252.222,68.453 253.365,68.453 255.016,66.802 U4.1 257.175,66.802 261.493,71.12 L2.1
NetC33_2: C33.2 U4.2 | length 4.9
  Top Layer w0.254: C33.2 254.203,65.532 U4.2
NetC34_1: C34.1 C35.1 D3.2 F1.1 L2.2 R6.1 | length 55.9
  Top Layer w0.254: D3.2 242.951,62.983 F1.1 247.606,60.951 250.772,57.785 v1(253.619,57.785) ; L2.2 C35.1@266.822,74.575 ; C35.1 266.902,74.549 v1(268.859,74.549) ; R6.1@267.297,65.405 v1(270.256,65.405)
  Bottom Layer w0.254: v1(253.619,57.785) 265.176,57.785 270.256,62.865 v1(270.256,65.405) 270.256,73.152 v1(268.859,74.549)
NetC37_1: C37.1 C38.1 C39.1 J6.1 R5.1 U4.8 | length 42.3
  Top Layer w0.254: v1(249.809,61.468) 250.571,60.706 C37.1 ; J6.1 251.317,77.089 C39.1 C38.1 252.476,71.882 249.809,69.215 v1(249.809,64.262) R5.1 ; v1(260.35,66.167) 260.985,66.802 U4.8
  Bottom Layer w0.254: v1(249.809,64.262) v1(249.809,61.468) 255.905,61.468 257.048,60.325 258.191,60.325 260.35,62.484 v1(260.35,66.167)
NetC41_2: C41.2 D4.K | length 1.5
  Top Layer w0.254: C41.2@267.386,40.767 D4.K
NetC43_2: C43.2 R10.1 | length 1.7
  Top Layer w0.254: R10.1 257.251,56.261 C43.2
NetD1_A: D1.A U5.110 | length 7.5
  Top Layer w0.254: U5.110 306.474,69.827 308.148,71.501 D1.A
NetD1_K: D1.K R1.1 | length 1.6
  Top Layer w0.254: D1.K R1.1
NetD2_A: D2.A P1.2 U5.109 | length 18.3
  Top Layer w0.254: v1(304.292,72.136) P1.2 ; U5.109 306.974,69.357 v1(308.102,70.485) 308.864,69.723 D2.A
  Bottom Layer w0.254: v1(304.292,72.136) 305.943,70.485 v1(308.102,70.485)
NetD2_K: D2.K R2.1 | length 1.7
  Top Layer w0.254: D2.K R2.1
NetD4_A: D4.A R7.2 | length 1.7
  Top Layer w0.254: D4.A 272.11,40.767 R7.2
NetJ4_2: J4.2 U5.75 | length 31.6
  Top Layer w0.254: U5.75 311.267,49.032 312.039,48.26 312.039,41.275 313.944,39.37 322.961,39.37 325.81,36.521 J4.2
NetJ4_3: J4.3 U5.76 | length 30.9
  Top Layer w0.254: U5.76 311.783,49.532 312.42,48.895 312.42,42.037 314.452,40.005 323.977,40.005 325.461,38.521 J4.3
NetJ6_2: J6.2 J6.3 | length 5.9
  Top Layer w0.254: J6.2 243.815,76.733 J6.3
NetP1_4: P1.4 U5.105 | length 26.7
  Top Layer w0.254: v1(308.991,69.088) 308.991,68.834 310.261,67.564 310.261,67.056 309.753,66.548 308.864,66.548 308.205,65.889 308.205,64.032 U5.105
  Bottom Layer w0.254: P1.4 299.212,78.613 304.038,73.787 309.753,73.787 310.261,73.279 310.261,72.644 308.991,71.374 v1(308.991,69.088)
NetR3_1: R3.1 U5.138 | length 4.8
  Top Layer w0.254: U5.138 292.474,71.113 R3.1
NetR5_2: R5.2 U4.3 | length 4.2
  Top Layer w0.254: R5.2 U4.3
NetR6_2: R6.2 R9.1 U4.5 | length 10.3
  Top Layer w0.254: U4.5 264.22,60.706 264.922,60.706 R9.1 265.697,64.503 R6.2
NetR8_1: R8.1 U4.7 | length 6.9
  Top Layer w0.254: U4.7 v1(263.398,65.532) ; v1(267.335,66.929) R8.1
  Bottom Layer w0.254: v1(263.398,65.532) 265.938,65.532 v1(267.335,66.929)
NetU1_2: U1.2 U5.85 | length 23.6
  Top Layer w0.177: v1(306.832,62.484) 306.77,62.422 306.77,61.666 306.805,61.631 306.805,55.881 307.34,55.346 307.34,54.991 308.299,54.032 U5.85 ; v1(314.452,62.357) 314.579,62.484 314.706,62.484 315.68,63.458 315.68,64.393 317.909,66.623 U1.2
  Bottom Layer w0.177: v1(306.832,62.484) 314.325,62.484 v1(314.452,62.357)
NetU1_4: U1.4 U5.86 | length 22
  Top Layer w0.177: v1(307.213,61.849) 307.086,61.722 307.086,55.998 308.552,54.532 U5.86 ; v1(315.468,62.103) 316.369,63.004 316.369,64.401 316.992,65.024 ; 316.992,65.023 U1.4
  Bottom Layer w0.177: v1(307.213,61.849) 307.721,61.849 307.948,62.076 314.107,62.076 314.269,61.914 314.635,61.914 315.078,62.357 315.214,62.357 v1(315.468,62.103)
NetU1_5: U1.5 U5.114 | length 20.5
  Top Layer w0.177: U5.114 304.474,67.11 304.909,66.675 v1(304.927,66.675) ; U1.5 319.366,64.223 320.167,65.024 320.167,65.795 320.105,65.857 320.105,66.285 320.167,66.346 v1(320.167,66.548)
  Bottom Layer w0.177: v1(304.927,66.675) 305.066,66.536 320.155,66.536 v1(320.167,66.548)
NetU1_7: U1.7 U5.115 | length 25
  Top Layer w0.177: U5.115 303.974,66.104 v1(304.038,66.04) ; U1.7 319.29,62.623 321.691,65.024 v1(321.691,66.04)
  Bottom Layer w0.177: v1(304.038,66.04) v1(321.691,66.04)
NetU1_8: U1.8 U5.58 | length 33.1
  Top Layer w0.177: U5.58 299.974,47.498 300.228,47.752 300.228,48.387 300.671,48.83 300.671,60.008 v1(300.988,60.325) ; v1(316.484,61.214) 316.585,61.214 316.611,61.188 317.246,61.823 U1.8
  Bottom Layer w0.177: v1(300.988,60.325) 301.153,60.49 303.941,60.49 304.288,60.144 307.413,60.144 308.483,61.214 313.777,61.214 313.92,61.071 316.341,61.071 v1(316.484,61.214)
NetU1_10: U1.10 U5.59 | length 38.5
  Top Layer w0.177: U5.59 300.509,45.867 300.509,48.271 300.952,48.713 300.952,48.73 v1(301.752,49.53) ; U1.10 318.129,60.198 319.024,60.198 322.834,56.388 v1(322.834,49.911)
  Bottom Layer w0.177: v1(301.752,49.53) 302.244,49.53 302.813,50.1 322.796,50.1 322.834,50.061 v1(322.834,49.911)
NetU1_11: U1.11 U5.60 | length 36.1
  Top Layer w0.177: U5.60 300.974,47.863 v1(302.006,48.895) ; U1.11 319.164,59.423 322.072,56.515 322.072,49.784 v1(322.199,49.657)
  Bottom Layer w0.177: v1(302.006,48.895) 302.83,49.719 322.137,49.719 v1(322.199,49.657)
NetU1_13: U1.13 U5.63 | length 32.6
  Top Layer w0.177: U5.63 302.474,48.22 v1(303.276,49.022) ; U1.13 319.24,57.823 321.691,55.372 321.691,49.53 v1(321.437,49.276)
  Bottom Layer w0.177: v1(303.276,49.022) 303.53,49.276 v1(321.437,49.276)
NetU1_15: U1.15 U5.141 | length 33.4
  Top Layer w0.177: U5.141 290.957,67.715 290.957,65.405 v1(291.211,65.151) ; v1(316.103,56.896) 316.103,56.693 316.573,56.223 U1.15
  Bottom Layer w0.177: v1(291.211,65.151) 291.599,65.151 294.344,62.406 294.387,62.406 294.755,62.037 294.755,61.995 299.793,56.958 316.041,56.958 v1(316.103,56.896)
NetU1_16: U1.16 U5.26 | length 32.9
  Top Layer w0.177: U5.26 v1(290.126,53.032) ; v1(315.722,52.832) 315.722,54.102 317.043,55.423 U1.16
  Bottom Layer w0.177: v1(290.126,53.032) 290.387,52.77 290.576,52.959 290.703,52.832 v1(315.722,52.832)
NetU1_17: U1.17 U5.132 | length 33.1
  Top Layer w0.177: U5.132@295.402,67.66 295.529,67.533 v1(295.529,60.198) ; v1(316.357,53.975) 316.458,53.975 317.106,54.623 U1.17
  Bottom Layer w0.177: v1@295.64,60.087 295.64,59.563 301.228,53.975 v1(316.357,53.975)
NetU1_18: U1.18 U5.49 | length 27.6
  Top Layer w0.177: U5.49@295.529,45.887 v1(295.529,48.133) ; v1(316.484,52.705) 316.484,53.051 317.256,53.823 U1.18 U1.18@318.299,53.823
  Bottom Layer w0.177: v1(295.529,48.133) 299.785,52.389 316.168,52.389 v1(316.484,52.705)
NetU1_19: U1.19 U5.136 | length 37.7
  Top Layer w0.177: v1(293.116,62.357) 293.116,66.752 293.342,66.977 293.342,67.6 U5.136 ; U1.19 318.961,53.023 v1(319.786,53.848)
  Bottom Layer w0.177: v1(293.116,62.357) 293.941,61.531 294.821,61.531 300.5,55.853 307.875,55.853 309.245,54.483 319.151,54.483 v1(319.786,53.848)
NetU1_20: U1.20 U5.89 | length 16.6
  Top Layer w0.177: U5.89@309.174,55.9 310.261,55.9 310.535,55.626 v1@311.365,55.626 ; U1.20 319.304,52.223 320.548,53.467 320.548,55.245 v1(320.167,55.626)
  Bottom Layer w0.177: v1(311.15,55.626) v1(320.167,55.626)
NetU1_21: U1.21 U5.90 | length 18.4
  Top Layer w0.177: U5.90@309.191,56.515 v1(310.388,56.515) ; U1.21 319.139,51.423 321.056,53.34 v1(321.056,54.864)
  Bottom Layer w0.177: v1(310.388,56.515) 310.707,56.196 310.707,55.443 310.967,55.183 311.333,55.183 311.495,55.345 319.822,55.345 319.984,55.183 320.737,55.183 v1(321.056,54.864)
NetU1_22: U1.22 U5.56 | length 27.1
  Top Layer w0.177: v1(298.958,47.498) 298.974,47.482 U5.56 ; U1.22 318.82,50.623 320.548,48.895 320.548,48.641 v1(320.167,48.26)
  Bottom Layer w0.177: v1(298.958,47.498) 299.72,48.26 v1(320.167,48.26)
NetU1_23: U1.23 U5.10 | length 39.3
  Top Layer w0.177: U5.10 292.409,61.032 293.751,59.69 v1(298.704,59.69) ; v1(312.801,60.071) 312.801,56.531 314.225,55.107 314.225,55.091 314.325,54.991 314.325,52.848 317.35,49.823 U1.23
  Bottom Layer w0.177: v1(298.704,59.69) 298.769,59.755 301.463,59.755 301.752,60.044 303.99,60.044 304.171,59.863 309.324,59.863 309.505,60.044 312.546,60.044 312.573,60.071 v1(312.801,60.071)
NetU1_24: U1.24 U5.11 | length 39.1
  Top Layer w0.177: U5.11 292.02,60.532 293.624,58.928 v1(298.958,58.928) ; v1(312.293,59.563) 312.42,59.436 312.42,56.515 313.944,54.991 313.944,52.832 317.753,49.023 U1.24
  Bottom Layer w0.177: v1(298.958,58.928) 299.504,59.474 312.204,59.474 v1(312.293,59.563)
NetU1_25: U1.25 U5.12 | length 38.8
  Top Layer w0.177: U5.12 287.407,59.9 288.029,59.9 288.111,59.817 292.338,59.817 293.669,58.485 299.141,58.485 299.457,58.801 v1(299.847,58.801) ; v1(311.173,58.547) 311.785,58.547 312.139,58.193 312.139,56.399 313.593,54.945 313.593,52.539 317.909,48.223 U1.25
  Bottom Layer w0.177: v1(299.847,58.801) 300.228,59.182 310.538,59.182 v1(311.173,58.547)
NetU1_26: U1.26 U5.13 | length 38.6
  Top Layer w0.177: U5.13@287.406,59.4 290.041,59.4 290.139,59.498 292.26,59.498 293.591,58.166 v1(299.72,58.166) ; v1(311.582,58.098) 311.777,57.904 311.777,56.363 313.312,54.828 313.312,52.02 317.477,47.856 318.104,47.856 U1.26
  Bottom Layer w0.177: v1(299.72,58.166) 299.847,58.293 300.042,58.098 v1(311.582,58.098)
NetU1_29: U1.29 U5.14 | length 49.8
  Top Layer w0.177: U5.14@287.297,59.055 v1(290.322,59.055) ; v1(325.247,53.213) 325.247,52.578 326.136,51.689 326.136,49.022 327.735,47.423 U1.29
  Bottom Layer w0.177: v1(290.322,59.055) 295.821,53.556 316.022,53.556 316.045,53.532 316.54,53.532 316.563,53.556 319.189,53.556 319.405,53.34 323.493,53.34 323.708,53.556 324.904,53.556 v1(325.247,53.213)
NetU1_30: U1.30 U5.17 | length 48.2
  Top Layer w0.177: U5.17 289.941,57.531 v1(290.449,57.023) ; v1(325.882,52.705) 325.882,52.574 326.644,51.812 326.644,49.412 327.833,48.223 U1.30
  Bottom Layer w0.177: v1(290.449,57.023) 294.197,53.275 315.905,53.275 315.928,53.251 316.563,53.251 317.11,52.705 v1(325.882,52.705)
NetU1_31: U1.31 U5.50 | length 37.6
  Top Layer w0.177: U5.50 295.974,46.454 296.799,47.279 v1(296.799,48.387) ; v1(327.406,49.276) 327.659,49.023 U1.31
  Bottom Layer w0.177: v1(296.799,48.387) 299.085,48.387 301.117,50.419 326.263,50.419 v1(327.406,49.276)
NetU1_32: U1.32 U5.53 | length 36.9
  Top Layer w0.177: U5.53 v1(297.474,48.982) ; v1(327.533,49.911) 327.621,49.823 U1.32
  Bottom Layer w0.177: v1(297.474,48.982) 299.283,48.982 301.061,50.76 326.684,50.76 v1(327.533,49.911)
NetU1_33: U1.33 U5.54 | length 36.5
  Top Layer w0.177: U5.54 297.974,46.731 298.106,46.863 298.106,49.44 v1(298.323,49.657) ; v1(327.66,50.673) 327.71,50.623 U1.33
  Bottom Layer w0.177: v1(298.323,49.657) 299.56,49.657 300.957,51.054 327.279,51.054 v1(327.66,50.673)
NetU1_34: U1.34 U5.55 | length 36.3
  Top Layer w0.177: U5.55 298.474,48.641 299.085,49.252 v1(299.085,50.165) ; v1(328.168,51.435) 328.18,51.423 U1.34
  Bottom Layer w0.177: v1(299.085,50.165) 299.847,50.927 300.355,50.927 301.09,51.662 327.395,51.662 327.422,51.689 327.914,51.689 v1(328.168,51.435)
NetU1_35: U1.35 U5.57 | length 36.3
  Top Layer w0.177: U5.57 299.528,45.886 299.528,50.992 300.224,51.689 v1(300.228,51.689) ; v1(327.559,52.223) U1.35
  Bottom Layer w0.177: v1(300.228,51.689) 300.482,51.943 327.279,51.943 v1(327.559,52.223)
NetU1_37: U1.37 U5.135 | length 47.8
  Top Layer w0.177: v1(293.878,65.913) U5.135@293.878,67.636 ; v1(325.12,65.532) 325.312,65.34 325.312,57.094 327.533,54.873 327.533,54.864 328.574,53.823 U1.37
  Bottom Layer w0.177: v1(293.878,65.913) 294.259,65.532 v1(325.12,65.532)
NetU1_38: U1.38 U5.93 | length 23
  Top Layer w0.177: U5.93 309.167,58.039 310.642,58.039 311.277,57.404 v1(311.277,56.515) ; v1(327.66,55.372) 328.409,54.623 U1.38
  Bottom Layer w0.177: v1(311.277,56.515) 311.277,56.388 311.504,56.161 326.871,56.161 v1(327.66,55.372)
NetU1_39: U1.39 U5.142 | length 50.6
  Top Layer w0.177: U5.142 290.607,67.599 290.607,65.13 291.22,64.516 292.1,64.516 v1(292.561,64.897) ; v1@326.137,65.025 326.137,58.165 328.879,55.423 U1.39
  Bottom Layer w0.177: v1(292.561,64.897) 292.754,65.089 326.074,65.089 v1(326.136,65.151)
NetU1_42: U1.42 U5.64 | length 47.8
  Top Layer w0.177: v1(302.895,61.341) 302.895,60.325 304.546,58.674 304.546,48.156 303.022,46.632 U5.64@303.022,45.832 ; v1(328.041,57.785) 328.079,57.823 U1.42
  Bottom Layer w0.177: v1(302.895,61.341) 303.031,61.341 303.601,60.771 304.058,60.771 304.404,60.425 307.297,60.425 308.367,61.495 313.893,61.495 314.036,61.352 315.987,61.352 316.865,62.23 324.739,62.23 328.041,58.928 v1(328.041,57.785)
NetU1_44: U1.44 U5.65 | length 45.2
  Top Layer w0.177: U5.65 303.468,45.832 303.403,45.898 303.403,46.383 304.927,47.907 304.927,54.978 304.838,55.067 304.838,59.525 303.784,60.579 v1(303.784,61.214) ; v1(328.308,59.423) U1.44
  Bottom Layer w0.177: v1(303.784,61.214) 304.012,61.214 304.52,60.706 307.18,60.706 308.25,61.776 314.01,61.776 314.152,61.633 315.76,61.633 316.638,62.511 324.855,62.511 326.152,61.214 326.399,61.214 328.19,59.423 v1(328.308,59.423)
NetU1_45: U1.45 U5.66 | length 46.5
  Top Layer w0.177: v1(303.657,62.484) 303.657,61.975 305.119,60.513 305.119,55.183 305.308,54.994 305.308,47.788 303.974,46.454 U5.66 ; v1(327.914,60.325) 327.914,60.223 U1.45
  Bottom Layer w0.177: v1(303.657,62.484) 304.038,62.484 304.419,62.103 305.824,62.103 306.647,62.927 307.015,62.927 307.119,62.822 308.243,62.822 308.285,62.865 324.899,62.865 325.661,62.103 326.898,62.103 327.914,61.087 v1(327.914,60.325)
NetU1_47: U1.47 U5.67 | length 43.8
  Top Layer w0.177: U5.67 304.474,46.537 305.689,47.752 305.689,55.01 305.4,55.299 305.4,61.049 304.8,61.649 v1(304.8,62.611) ; v1(327.914,61.849) 327.94,61.823 U1.47
  Bottom Layer w0.177: v1(304.8,62.611) 305.897,62.611 306.151,62.865 306.189,62.865 306.531,63.208 307.132,63.208 307.236,63.103 308.126,63.103 308.169,63.146 325.015,63.146 325.296,62.865 326.898,62.865 v1(327.914,61.849)
NetU1_48: U1.48 U5.68 | length 43.8
  Top Layer w0.177: U5.68 304.974,46.454 306.07,47.55 306.07,55.027 305.681,55.416 305.681,61.166 305.546,61.3 305.546,62.49 305.054,62.983 v1(305.054,63.246) ; v1(327.914,62.738) 328.029,62.623 U1.48
  Bottom Layer w0.177: v1(305.054,63.246) 306.172,63.246 306.415,63.489 307.248,63.489 307.352,63.384 308.01,63.384 308.053,63.427 325.132,63.427 325.313,63.246 326.914,63.246 327.422,62.738 v1(327.914,62.738)
NetU1_50: U1.50 U5.77 | length 40.9
  Top Layer w0.177: v1(305.435,63.754) 305.662,63.527 305.662,62.833 305.827,62.667 305.827,61.417 305.962,61.282 305.962,55.532 306.386,55.109 306.386,51.627 307.981,50.032 U5.77 ; v1(327.914,64.008) 328.129,64.223 U1.50
  Bottom Layer w0.177: v1(305.435,63.754) 305.451,63.77 307.364,63.77 307.468,63.665 307.894,63.665 307.982,63.754 327.66,63.754 v1(327.914,64.008)
NetU1_51: U1.51 U5.78 | length 40.6
  Top Layer w0.177: v1(305.943,64.389) 305.943,62.949 306.108,62.784 306.108,61.533 306.243,61.398 306.243,55.649 306.705,55.187 306.705,51.816 307.989,50.532 U5.78 ; v1(327.914,65.024) v1(327.914,65.024) U1.51
  Bottom Layer w0.177: v1(305.943,64.389) 306.324,64.389 306.513,64.2 307.7,64.2 307.866,64.035 326.925,64.035 v1(327.914,65.024)
NetU1_53: U1.53 U5.79 | length 40.4
  Top Layer w0.177: v1(306.705,64.643) 306.705,64.262 306.389,63.946 306.389,61.649 306.524,61.515 306.524,55.765 307.059,55.23 307.059,51.97 307.997,51.032 U5.79 ; v1(328.041,66.675) 328.093,66.623 U1.53
  Bottom Layer w0.177: v1(306.705,64.643) 326.136,64.643 326.39,64.389 327.469,65.468 327.469,66.103 v1(328.041,66.675)
NetU2_1: U2.1 U5.111 | length 27.2
  Top Layer w0.254: U5.111 305.974,70.008 309.432,73.466 316.036,73.466 316.992,74.422 316.992,82.804 315.817,83.979 U2.1
NetU2_2: U2.2 U5.112 | length 24.8
  Top Layer w0.254: U5.112 305.474,70.27 309.499,74.295 315.849,74.295 316.357,74.803 316.357,81.28 315.158,82.479 U2.2
NetU2_3: U2.3 U5.116 | length 18.5
  Top Layer w0.254: U5.116 303.474,69.792 311.531,77.849 311.531,80.28 312.23,80.979 U2.3
NetU2_5: U2.5 U5.113 | length 14.9
  Top Layer w0.254: U5.113 304.974,70.786 312.167,77.979 U2.5
NetU2_6: U2.6 U5.98 | length 21.4
  Top Layer w0.254: v1(308.61,67.818) 306.982,66.19 306.982,65.427 307.236,65.173 307.236,62.76 307.694,62.302 307.694,61.329 308.255,60.768 308.261,60.768 308.403,60.626 308.403,60.532 U5.98 ; v1(311.658,76.454) U2.6@313.792,76.454
  Bottom Layer w0.254: v1(308.61,67.818) 311.658,70.866 v1(311.658,76.454)
NetU2_7: U2.7 U5.99 | length 19
  Top Layer w0.254: U5.99 309.08,61.126 308.403,61.126 308.052,61.477 308.052,62.451 307.594,62.909 307.594,65.322 307.34,65.576 307.34,65.913 308.61,67.183 v1(309.245,67.183) ; v1(312.166,74.93) U2.7@313.768,74.93
  Bottom Layer w0.254: v1(309.245,67.183) 312.166,70.104 v1(312.166,74.93)
NetU2_9: U2.9 U5.124 | length 33.2
  Top Layer w0.254: U5.124@299.466,67.74 v1(299.466,70.485) ; v1(309.626,72.898) 315.722,72.898 315.849,72.771 319.557,76.479 U2.9
  Bottom Layer w0.254: v1(299.466,70.485) 301.879,72.898 v1(309.626,72.898)
NetU5_1: U5.1
NetU5_2: U5.2
NetU5_3: U5.3
NetU5_4: U5.4
NetU5_5: U5.5
NetU5_6: U5.6
NetU5_7: U5.7
NetU5_8: U5.8
NetU5_9: U5.9
NetU5_18: U5.18
NetU5_19: U5.19
NetU5_20: U5.20
NetU5_21: U5.21
NetU5_22: U5.22
NetU5_27: U5.27
NetU5_28: U5.28
NetU5_29: U5.29
NetU5_34: U5.34
NetU5_35: U5.35
NetU5_36: U5.36
NetU5_37: U5.37
NetU5_40: U5.40
NetU5_41: U5.41
NetU5_42: U5.42
NetU5_43: U5.43
NetU5_44: U5.44
NetU5_45: U5.45
NetU5_46: U5.46
NetU5_47: U5.47
NetU5_48: U5.48
NetU5_69: U5.69
NetU5_70: U5.70
NetU5_73: U5.73
NetU5_74: U5.74
NetU5_80: U5.80
NetU5_81: U5.81
NetU5_82: U5.82
NetU5_87: U5.87
NetU5_88: U5.88
NetU5_91: U5.91
NetU5_92: U5.92
NetU5_96: U5.96
NetU5_97: U5.97
NetU5_100: U5.100
NetU5_101: U5.101
NetU5_102: U5.102
NetU5_103: U5.103
NetU5_104: U5.104
NetU5_117: U5.117
NetU5_118: U5.118
NetU5_119: U5.119
NetU5_122: U5.122
NetU5_123: U5.123
NetU5_125: U5.125
NetU5_126: U5.126
NetU5_127: U5.127
NetU5_128: U5.128
NetU5_129: U5.129
NetU5_133: U5.133
NetU5_134: U5.134
NetU5_137: U5.137
NetU5_139: U5.139
NetU5_140: U5.140
pads on no net: C43.1 J1.1 J1.2 J1.3 J1.4 J1.5 J1.6 J1.7 J1.8 J1.9 J1.10 J1.11 J1.12 J1.13 J1.14 J1.15 J1.16 J1.17 J1.18 J1.19 J1.20 J1.21 J1.22 J1.23 J1.24 J1.25 J1.26 J1.27 J1.28 J1.29 J1.30 J1.31 J1.32 J1.33 J1.34 J1.35 J1.36 J1.37 J1.38 J2.1 J2.2 J2.3 J2.4 J2.5 J2.6 J2.7 J2.8 J2.9 J2.10 J2.11 J2.12 J2.13 J2.14 J2.15 J2.16 J2.17 J2.18 J2.19 J2.20 J2.21 J2.22 J2.23 J2.24 J2.25 J2.26 J2.27 J2.28 J2.29 J2.30 J2.31 J2.32 J2.33 J2.34 J2.35 J2.36 J2.37 J2.38 U1.36 U1.40 U2.13 U2.14 U4.6 Y2.2 Y2.4

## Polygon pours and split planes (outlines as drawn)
no net on Top Layer "Top Layer-No Net" (solid, pour order 0): 240,30 240,90 340,90 340,30
no net on Bottom Layer "Bottom Layer" (solid, pour order 1): 240,30 240,90 340,90 340,30

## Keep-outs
Keep-Out Layer:
  lines w0.254: 241,31 241,89 339,89 339,31 241,31

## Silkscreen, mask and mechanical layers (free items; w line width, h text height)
Mechanical 1:
  the board outline again, w0.254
